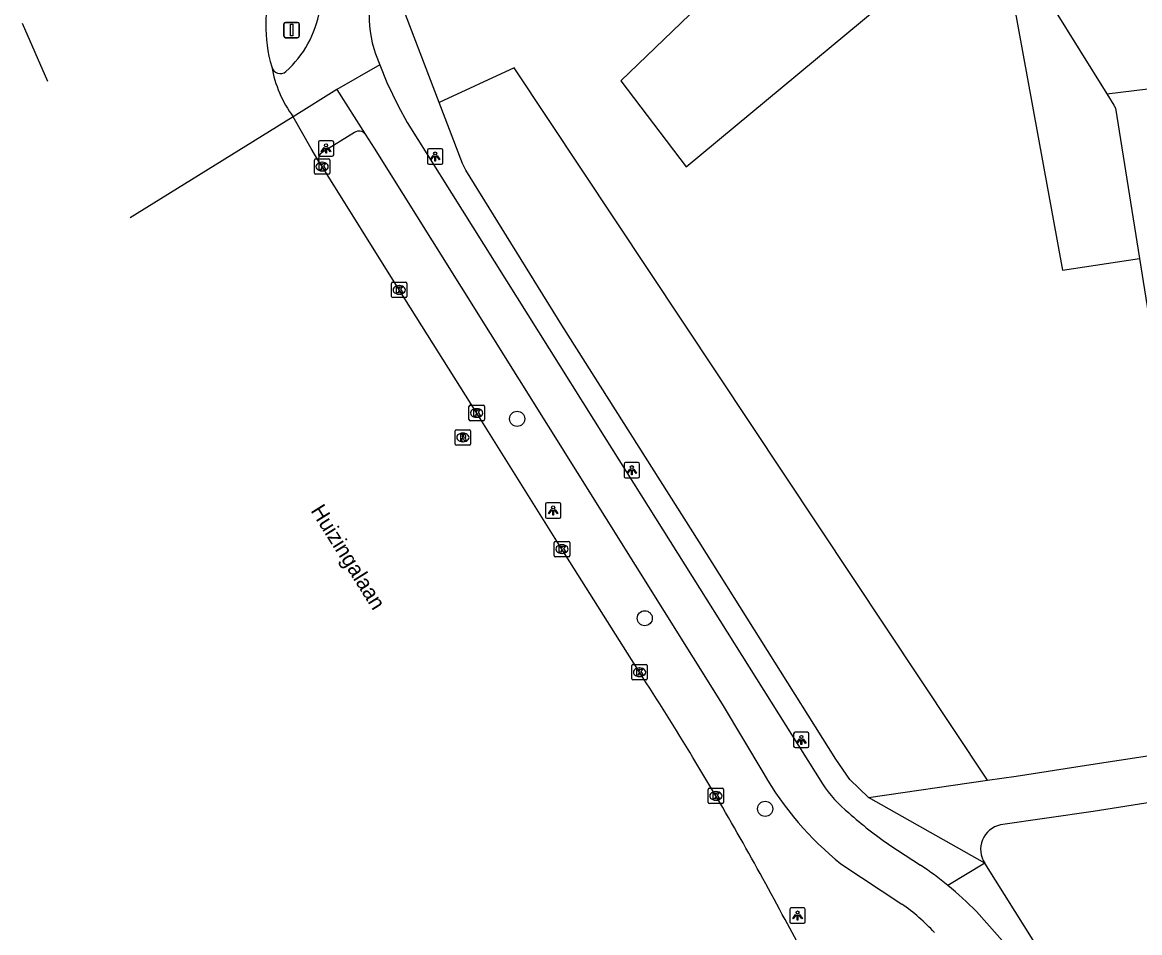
# Model space of a CAD drawing. Extents: x 160077 to 160945, y 386481 to 387498.
# Drawn here: x 160077 to 160149.7, y 387264.4 to 387323.5 of the extents above; entities that cross this region are included whole.
import ezdxf

# ---------------------------------------------------------------- set-up
doc = ezdxf.new("R2010")
doc.units = 0
for name, color, linetype in [('IMGEO_Boom', 7, 'Continuous'), ('IMGEO_Fietspad_gesloten', 7, 'Continuous'), ('IMGEO_Groenvoorziening', 7, 'Continuous'), ('IMGEO_Kolk', 7, 'Continuous'), ('IMGEO_Lichtpunt', 7, 'Continuous'), ('IMGEO_Openbare_ruimte_label', 7, 'Continuous'), ('IMGEO_OVBaan_gesloten', 7, 'Continuous'), ('IMGEO_Portaal', 7, 'Continuous'), ('IMGEO_Rijbaan_regionaal_gesloten', 7, 'Continuous'), ('IMGEO_Rioolput', 7, 'Continuous'), ('IMGEO_Voetpad_gesloten', 7, 'Continuous'), ('IMGEO_Voetpad_open', 7, 'Continuous')]:
    doc.layers.add(name, color=color, linetype=linetype)

msp = doc.modelspace()

# ---------------------------------------------------------------- linework, layer by layer
at = {"layer": 'IMGEO_Boom'}
for centre in [(160109.211, 387297.771), (160117.506, 387284.806), (160125.333, 387272.416)]:
    msp.add_circle(centre, 0.489, dxfattribs=at)
at = {"layer": 'IMGEO_Fietspad_gesloten'}
for points in [[(160100.002, 387321.494), (160100.284, 387320.786)], [(160100.284, 387320.786), (160097.499, 387319.172)], [(160100.284, 387320.786), (160100.745, 387319.628), (160101.473, 387318.123), (160102.066, 387317.033), (160114.864, 387296.614), (160129.06, 387274.05)], [(160097.499, 387319.172), (160094.645, 387317.405)], [(160097.499, 387319.172), (160099.341, 387316.28)], [(160099.341, 387316.28), (160099.906, 387315.367), (160122.542, 387279.222), (160125.245, 387274.696)], [(160133.446, 387270.057), (160135.422, 387268.762)], [(160130.263, 387268.841), (160134.209, 387266.225)], [(160139.072, 387265.739), (160141.59, 387262.907), (160159.923, 387233.732), (160180.666, 387200.687)]]:
    msp.add_lwpolyline(points, dxfattribs=at)
for centre, radius, start, end in [((160089.532, 387325.502), 6.943, 312.05353, 350.24641), ((160107.216, 387323.943), 7.619, 176.26365, 198.74719), ((160093.812, 387320.778), 0.568, 191.60509, 310.6373), ((160143.301, 387285.093), 20.836, 209.93439, 231.26175), ((160135.924, 387278.518), 8.191, 213.06275, 231.00172), ((160147.775, 387291.107), 25.464, 228.10281, 235.75693), ((160122.078, 387248.926), 23.906, 50.71415, 56.06934), ((160122.195, 387249.07), 23.721, 44.64408, 50.7134), ((160127.505, 387256.376), 11.914, 42.12371, 55.75976)]:
    msp.add_arc(centre, radius, start, end, dxfattribs=at)
at = {"layer": 'IMGEO_Groenvoorziening'}
for points in [[(160133.36, 387341.629), (160133.048, 387341.231), (160135, 387338.07), (160115.943, 387319.74), (160120.193, 387314.153), (160139.057, 387329.83), (160141.124, 387326.758), (160144.653, 387307.431), (160149.674, 387308.189)], [(160140.514, 387330.194), (160147.536, 387318.896)], [(160139.785, 387274.28), (160109.024, 387320.599), (160104.15, 387318.343)]]:
    msp.add_lwpolyline(points, dxfattribs=at)
at = {"layer": 'IMGEO_Kolk'}
for p, q in [((160096.03, 387313.741), (160096.03, 387314.593)), ((160096.105, 387314.667), (160096.957, 387314.667)), ((160097.031, 387314.593), (160097.031, 387313.741)), ((160096.541, 387313.887), (160096.516, 387313.887)), ((160096.518, 387314.447), (160096.543, 387314.447)), ((160096.957, 387313.667), (160096.105, 387313.667)), ((160101.12, 387306.651), (160101.972, 387306.651)), ((160101.045, 387305.725), (160101.045, 387306.577)), ((160101.556, 387305.871), (160101.531, 387305.871)), ((160101.533, 387306.431), (160101.558, 387306.431)), ((160102.046, 387306.577), (160102.046, 387305.725)), ((160101.972, 387305.651), (160101.12, 387305.651)), ((160106.155, 387298.648), (160107.007, 387298.648)), ((160106.08, 387297.722), (160106.08, 387298.574)), ((160106.568, 387298.428), (160106.593, 387298.428)), ((160107.081, 387298.574), (160107.081, 387297.722)), ((160107.007, 387297.648), (160106.155, 387297.648)), ((160106.591, 387297.868), (160106.566, 387297.868)), ((160111.625, 387288.875), (160111.625, 387289.727)), ((160111.7, 387289.801), (160112.552, 387289.801)), ((160112.113, 387289.581), (160112.138, 387289.581)), ((160112.626, 387289.727), (160112.626, 387288.875)), ((160112.552, 387288.801), (160111.7, 387288.801)), ((160112.136, 387289.021), (160112.111, 387289.021)), ((160116.664, 387280.872), (160116.664, 387281.724)), ((160116.739, 387281.798), (160117.591, 387281.798)), ((160117.152, 387281.578), (160117.177, 387281.578)), ((160117.665, 387281.724), (160117.665, 387280.872)), ((160117.591, 387280.798), (160116.739, 387280.798)), ((160117.175, 387281.018), (160117.15, 387281.018)), ((160121.63, 387272.831), (160121.63, 387273.683)), ((160121.705, 387273.757), (160122.557, 387273.757)), ((160122.118, 387273.537), (160122.143, 387273.537)), ((160122.631, 387273.683), (160122.631, 387272.831)), ((160122.557, 387272.757), (160121.705, 387272.757)), ((160122.141, 387272.977), (160122.116, 387272.977))]:
    msp.add_line(p, q, dxfattribs=at)
for points in [[(160096.03, 387313.741), (160096.03, 387314.593)], [(160096.105, 387314.667), (160096.957, 387314.667)], [(160097.031, 387314.593), (160097.031, 387313.741)], [(160096.351, 387314.367), (160096.474, 387314.367), (160096.474, 387314.216), (160096.604, 387314.367), (160096.768, 387314.367), (160096.622, 387314.216), (160096.775, 387313.967), (160096.623, 387313.967), (160096.538, 387314.131), (160096.474, 387314.064), (160096.474, 387313.967), (160096.351, 387313.967), (160096.351, 387314.367)], [(160096.957, 387313.667), (160096.105, 387313.667)], [(160101.12, 387306.651), (160101.972, 387306.651)], [(160101.045, 387305.725), (160101.045, 387306.577)], [(160101.366, 387306.351), (160101.489, 387306.351), (160101.489, 387306.2), (160101.619, 387306.351), (160101.783, 387306.351), (160101.637, 387306.2), (160101.79, 387305.951), (160101.638, 387305.951), (160101.553, 387306.115), (160101.489, 387306.048), (160101.489, 387305.951), (160101.366, 387305.951), (160101.366, 387306.351)], [(160102.046, 387306.577), (160102.046, 387305.725)], [(160101.972, 387305.651), (160101.12, 387305.651)], [(160106.155, 387298.648), (160107.007, 387298.648)], [(160106.08, 387297.722), (160106.08, 387298.574)], [(160106.401, 387298.348), (160106.524, 387298.348), (160106.524, 387298.197), (160106.654, 387298.348), (160106.818, 387298.348), (160106.672, 387298.197), (160106.825, 387297.948), (160106.673, 387297.948), (160106.588, 387298.112), (160106.524, 387298.045), (160106.524, 387297.948), (160106.401, 387297.948), (160106.401, 387298.348)], [(160107.081, 387298.574), (160107.081, 387297.722)], [(160107.007, 387297.648), (160106.155, 387297.648)], [(160111.625, 387288.875), (160111.625, 387289.727)], [(160111.7, 387289.801), (160112.552, 387289.801)], [(160111.946, 387289.501), (160112.069, 387289.501), (160112.069, 387289.35), (160112.199, 387289.501), (160112.363, 387289.501), (160112.217, 387289.35), (160112.37, 387289.101), (160112.218, 387289.101), (160112.133, 387289.265), (160112.069, 387289.198), (160112.069, 387289.101), (160111.946, 387289.101), (160111.946, 387289.501)], [(160112.626, 387289.727), (160112.626, 387288.875)], [(160112.552, 387288.801), (160111.7, 387288.801)], [(160116.664, 387280.872), (160116.664, 387281.724)], [(160116.739, 387281.798), (160117.591, 387281.798)], [(160116.985, 387281.498), (160117.108, 387281.498), (160117.108, 387281.347), (160117.238, 387281.498), (160117.402, 387281.498), (160117.256, 387281.347), (160117.409, 387281.098), (160117.257, 387281.098), (160117.172, 387281.262), (160117.108, 387281.195), (160117.108, 387281.098), (160116.985, 387281.098), (160116.985, 387281.498)], [(160117.665, 387281.724), (160117.665, 387280.872)], [(160117.591, 387280.798), (160116.739, 387280.798)], [(160121.63, 387272.831), (160121.63, 387273.683)], [(160121.705, 387273.757), (160122.557, 387273.757)], [(160121.951, 387273.457), (160122.074, 387273.457), (160122.074, 387273.306), (160122.204, 387273.457), (160122.368, 387273.457), (160122.222, 387273.306), (160122.375, 387273.057), (160122.223, 387273.057), (160122.138, 387273.221), (160122.074, 387273.154), (160122.074, 387273.057), (160121.951, 387273.057), (160121.951, 387273.457)], [(160122.631, 387273.683), (160122.631, 387272.831)], [(160122.557, 387272.757), (160121.705, 387272.757)]]:
    msp.add_lwpolyline(points, dxfattribs=at)
for centre, start, end in [((160096.107, 387314.591), 91.55205, 178.44795), ((160096.107, 387314.591), 91.55205, 178.44795), ((160096.955, 387314.591), 1.55205, 88.44795), ((160096.955, 387314.591), 1.55205, 88.44795), ((160096.107, 387313.743), 181.55205, 268.44795), ((160096.107, 387313.743), 181.55205, 268.44795), ((160096.955, 387313.743), 271.55205, 358.44795), ((160096.955, 387313.743), 271.55205, 358.44795), ((160101.122, 387306.575), 91.55205, 178.44795), ((160101.122, 387306.575), 91.55205, 178.44795), ((160101.97, 387306.575), 1.55205, 88.44795), ((160101.97, 387306.575), 1.55205, 88.44795), ((160101.122, 387305.727), 181.55205, 268.44795), ((160101.122, 387305.727), 181.55205, 268.44795), ((160101.97, 387305.727), 271.55205, 358.44795), ((160101.97, 387305.727), 271.55205, 358.44795), ((160106.157, 387298.572), 91.55205, 178.44795), ((160106.157, 387298.572), 91.55205, 178.44795), ((160107.005, 387298.572), 1.55205, 88.44795), ((160107.005, 387298.572), 1.55205, 88.44795), ((160106.157, 387297.724), 181.55205, 268.44795), ((160106.157, 387297.724), 181.55205, 268.44795), ((160107.005, 387297.724), 271.55205, 358.44795), ((160107.005, 387297.724), 271.55205, 358.44795), ((160111.702, 387289.725), 91.55205, 178.44795), ((160111.702, 387289.725), 91.55205, 178.44795), ((160112.55, 387289.725), 1.55205, 88.44795), ((160112.55, 387289.725), 1.55205, 88.44795), ((160111.702, 387288.877), 181.55205, 268.44795), ((160111.702, 387288.877), 181.55205, 268.44795), ((160112.55, 387288.877), 271.55205, 358.44795), ((160112.55, 387288.877), 271.55205, 358.44795), ((160116.741, 387281.722), 91.55205, 178.44795), ((160116.741, 387281.722), 91.55205, 178.44795), ((160117.589, 387281.722), 1.55205, 88.44795), ((160117.589, 387281.722), 1.55205, 88.44795), ((160116.741, 387280.874), 181.55205, 268.44795), ((160116.741, 387280.874), 181.55205, 268.44795), ((160117.589, 387280.874), 271.55205, 358.44795), ((160117.589, 387280.874), 271.55205, 358.44795), ((160121.707, 387273.681), 91.55205, 178.44795), ((160121.707, 387273.681), 91.55205, 178.44795), ((160122.555, 387273.681), 1.55205, 88.44795), ((160122.555, 387273.681), 1.55205, 88.44795), ((160121.707, 387272.833), 181.55205, 268.44795), ((160121.707, 387272.833), 181.55205, 268.44795), ((160122.555, 387272.833), 271.55205, 358.44795), ((160122.555, 387272.833), 271.55205, 358.44795)]:
    msp.add_arc(centre, 0.0765, start, end, dxfattribs=at)
for centre, major_axis, ratio, start_param, end_param in [((160096.517, 387314.167), (-0.387, 0.002), 0.722429, 4.712389, 7.853982), ((160096.542, 387314.167), (-0.39, 0.002), 0.717154, 1.570796, 4.712389), ((160101.532, 387306.151), (-0.387, 0.002), 0.722429, 4.712389, 7.853982), ((160101.557, 387306.151), (-0.39, 0.002), 0.717154, 1.570796, 4.712389), ((160106.567, 387298.148), (-0.387, 0.002), 0.722429, 4.712389, 7.853982), ((160106.592, 387298.148), (-0.39, 0.002), 0.717154, 1.570796, 4.712389), ((160112.112, 387289.301), (-0.387, 0.002), 0.722429, 4.712389, 7.853982), ((160112.137, 387289.301), (-0.39, 0.002), 0.717154, 1.570796, 4.712389), ((160117.151, 387281.298), (-0.387, 0.002), 0.722429, 4.712389, 7.853982), ((160117.176, 387281.298), (-0.39, 0.002), 0.717154, 1.570796, 4.712389), ((160122.117, 387273.257), (-0.387, 0.002), 0.722429, 4.712389, 7.853982), ((160122.142, 387273.257), (-0.39, 0.002), 0.717154, 1.570796, 4.712389)]:
    msp.add_ellipse(centre, major_axis=major_axis, ratio=ratio, start_param=start_param, end_param=end_param, dxfattribs=at)
at = {"layer": 'IMGEO_Lichtpunt'}
for p, q in [((160096.29, 387315.75), (160096.29, 387314.943)), ((160096.29, 387315.75), (160096.29, 387314.943)), ((160097.192, 387315.845), (160096.384, 387315.845)), ((160097.192, 387315.845), (160096.384, 387315.845)), ((160097.286, 387314.943), (160097.286, 387315.75)), ((160097.286, 387314.943), (160097.286, 387315.75)), ((160104.286, 387315.321), (160103.478, 387315.321)), ((160104.286, 387315.321), (160103.478, 387315.321)), ((160096.384, 387314.849), (160097.192, 387314.849)), ((160096.384, 387314.849), (160097.192, 387314.849)), ((160103.384, 387315.226), (160103.384, 387314.419)), ((160103.384, 387315.226), (160103.384, 387314.419)), ((160104.38, 387314.419), (160104.38, 387315.226)), ((160104.38, 387314.419), (160104.38, 387315.226)), ((160103.478, 387314.325), (160104.286, 387314.325)), ((160103.478, 387314.325), (160104.286, 387314.325)), ((160116.166, 387294.833), (160116.166, 387294.026)), ((160116.166, 387294.833), (160116.166, 387294.026)), ((160117.068, 387294.928), (160116.26, 387294.928)), ((160117.068, 387294.928), (160116.26, 387294.928)), ((160117.162, 387294.026), (160117.162, 387294.833)), ((160117.162, 387294.026), (160117.162, 387294.833)), ((160116.26, 387293.932), (160117.068, 387293.932)), ((160116.26, 387293.932), (160117.068, 387293.932)), ((160111.053, 387292.215), (160111.053, 387291.408)), ((160111.053, 387292.215), (160111.053, 387291.408)), ((160111.955, 387292.31), (160111.147, 387292.31)), ((160111.955, 387292.31), (160111.147, 387292.31)), ((160112.049, 387291.408), (160112.049, 387292.215)), ((160112.049, 387291.408), (160112.049, 387292.215)), ((160111.147, 387291.314), (160111.955, 387291.314)), ((160111.147, 387291.314), (160111.955, 387291.314)), ((160127.186, 387277.296), (160127.186, 387276.489)), ((160127.186, 387277.296), (160127.186, 387276.489)), ((160128.088, 387277.391), (160127.28, 387277.391)), ((160128.088, 387277.391), (160127.28, 387277.391)), ((160128.182, 387276.489), (160128.182, 387277.296)), ((160128.182, 387276.489), (160128.182, 387277.296)), ((160127.28, 387276.395), (160128.088, 387276.395)), ((160127.28, 387276.395), (160128.088, 387276.395)), ((160127.841, 387265.978), (160127.033, 387265.978)), ((160127.841, 387265.978), (160127.033, 387265.978)), ((160126.939, 387265.883), (160126.939, 387265.076)), ((160126.939, 387265.883), (160126.939, 387265.076)), ((160127.935, 387265.076), (160127.935, 387265.883)), ((160127.935, 387265.076), (160127.935, 387265.883)), ((160127.033, 387264.982), (160127.841, 387264.982)), ((160127.033, 387264.982), (160127.841, 387264.982))]:
    msp.add_line(p, q, dxfattribs=at)
for points in [[(160096.664, 387315.414), (160096.703, 387315.386), (160096.515, 387315.124), (160096.477, 387315.151), (160096.664, 387315.414)], [(160096.766, 387315.366), (160096.813, 387315.366), (160096.813, 387315.044), (160096.766, 387315.044), (160096.766, 387315.366)], [(160096.876, 387315.386), (160096.914, 387315.413), (160097.101, 387315.151), (160097.062, 387315.123), (160096.876, 387315.386)], [(160103.758, 387314.89), (160103.797, 387314.862), (160103.609, 387314.6), (160103.571, 387314.627), (160103.758, 387314.89)], [(160103.86, 387314.842), (160103.907, 387314.842), (160103.907, 387314.52), (160103.86, 387314.52), (160103.86, 387314.842)], [(160103.97, 387314.862), (160104.008, 387314.889), (160104.195, 387314.627), (160104.156, 387314.599), (160103.97, 387314.862)], [(160116.54, 387294.497), (160116.579, 387294.469), (160116.391, 387294.207), (160116.353, 387294.234), (160116.54, 387294.497)], [(160116.642, 387294.449), (160116.689, 387294.449), (160116.689, 387294.127), (160116.642, 387294.127), (160116.642, 387294.449)], [(160116.752, 387294.469), (160116.79, 387294.496), (160116.977, 387294.234), (160116.938, 387294.206), (160116.752, 387294.469)], [(160111.427, 387291.879), (160111.466, 387291.851), (160111.278, 387291.589), (160111.24, 387291.616), (160111.427, 387291.879)], [(160111.529, 387291.831), (160111.576, 387291.831), (160111.576, 387291.509), (160111.529, 387291.509), (160111.529, 387291.831)], [(160111.639, 387291.851), (160111.677, 387291.878), (160111.864, 387291.616), (160111.825, 387291.588), (160111.639, 387291.851)], [(160127.56, 387276.96), (160127.599, 387276.932), (160127.411, 387276.67), (160127.373, 387276.697), (160127.56, 387276.96)], [(160127.662, 387276.912), (160127.709, 387276.912), (160127.709, 387276.59), (160127.662, 387276.59), (160127.662, 387276.912)], [(160127.772, 387276.932), (160127.81, 387276.959), (160127.997, 387276.697), (160127.958, 387276.669), (160127.772, 387276.932)], [(160127.313, 387265.547), (160127.352, 387265.519), (160127.164, 387265.257), (160127.126, 387265.284), (160127.313, 387265.547)], [(160127.415, 387265.499), (160127.462, 387265.499), (160127.462, 387265.177), (160127.415, 387265.177), (160127.415, 387265.499)], [(160127.525, 387265.519), (160127.563, 387265.546), (160127.75, 387265.284), (160127.711, 387265.256), (160127.525, 387265.519)]]:
    msp.add_lwpolyline(points, dxfattribs=at)
for centre in [(160096.789, 387315.548), (160103.883, 387315.024), (160116.665, 387294.631), (160111.552, 387292.013), (160127.685, 387277.094), (160127.438, 387265.681)]:
    msp.add_circle(centre, 0.0994, dxfattribs=at)
for centre, start, end in [((160096.384, 387315.75), 90, 180), ((160096.384, 387315.75), 90, 180), ((160097.192, 387315.75), 0, 90), ((160097.192, 387315.75), 0, 90), ((160103.478, 387315.226), 90, 180), ((160103.478, 387315.226), 90, 180), ((160104.286, 387315.226), 0, 90), ((160104.286, 387315.226), 0, 90), ((160096.384, 387314.943), 180, 270), ((160096.384, 387314.943), 180, 270), ((160097.192, 387314.943), 270, 0), ((160097.192, 387314.943), 270, 360), ((160103.478, 387314.419), 180, 270), ((160103.478, 387314.419), 180, 270), ((160104.286, 387314.419), 270, 0), ((160104.286, 387314.419), 270, 360), ((160116.26, 387294.833), 90, 180), ((160116.26, 387294.833), 90, 180), ((160117.068, 387294.833), 0, 90), ((160117.068, 387294.833), 0, 90), ((160116.26, 387294.026), 180, 270), ((160116.26, 387294.026), 180, 270), ((160117.068, 387294.026), 270, 0), ((160117.068, 387294.026), 270, 360), ((160111.147, 387292.215), 90, 180), ((160111.147, 387292.215), 90, 180), ((160111.955, 387292.215), 0, 90), ((160111.955, 387292.215), 0, 90), ((160111.147, 387291.408), 180, 270), ((160111.147, 387291.408), 180, 270), ((160111.955, 387291.408), 270, 0), ((160111.955, 387291.408), 270, 360), ((160127.28, 387277.296), 90, 180), ((160127.28, 387277.296), 90, 180), ((160128.088, 387277.296), 0, 90), ((160128.088, 387277.296), 0, 90), ((160127.28, 387276.489), 180, 270), ((160127.28, 387276.489), 180, 270), ((160128.088, 387276.489), 270, 0), ((160128.088, 387276.489), 270, 360), ((160127.033, 387265.883), 90, 180), ((160127.033, 387265.883), 90, 180), ((160127.841, 387265.883), 0, 90), ((160127.841, 387265.883), 0, 90), ((160127.033, 387265.076), 180, 270), ((160127.033, 387265.076), 180, 270), ((160127.841, 387265.076), 270, 0), ((160127.841, 387265.076), 270, 360)]:
    msp.add_arc(centre, 0.0946, start, end, dxfattribs=at)
at = {"layer": 'IMGEO_OVBaan_gesloten'}
msp.add_lwpolyline([(160078.711, 387319.696), (160077.046, 387323.47)], dxfattribs=at)
at = {"layer": 'IMGEO_Portaal'}
for p, q in [((160094.051, 387322.646), (160094.051, 387323.446)), ((160094.051, 387323.446), (160094.051, 387322.646)), ((160094.151, 387323.546), (160094.941, 387323.546)), ((160094.941, 387323.546), (160094.151, 387323.546)), ((160095.041, 387323.446), (160095.041, 387322.646)), ((160095.041, 387322.646), (160095.041, 387323.446)), ((160094.941, 387322.546), (160094.151, 387322.546)), ((160094.151, 387322.546), (160094.941, 387322.546))]:
    msp.add_line(p, q, dxfattribs=at)
msp.add_lwpolyline([(160094.471, 387323.421), (160094.621, 387323.421), (160094.621, 387322.671), (160094.471, 387322.671), (160094.471, 387323.421)], dxfattribs=at)
for centre, start, end in [((160094.151, 387323.446), 90, 180), ((160094.151, 387323.446), 90, 180), ((160094.941, 387323.446), 0, 90), ((160094.941, 387323.446), 360, 90), ((160094.151, 387322.646), 180, 270), ((160094.151, 387322.646), 180, 270), ((160094.941, 387322.646), 270, 0), ((160094.941, 387322.646), 270, 0)]:
    msp.add_arc(centre, 0.1, start, end, dxfattribs=at)
at = {"layer": 'IMGEO_Rijbaan_regionaal_gesloten'}
for points in [[(160094.645, 387317.405), (160084.061, 387310.833)], [(160096.318, 387314.501), (160095.816, 387315.349), (160094.645, 387317.405)], [(160117.165, 387281.298), (160112.126, 387289.301), (160106.581, 387298.148), (160101.546, 387306.151), (160096.531, 387314.167), (160096.318, 387314.501)], [(160162.84, 387197.364), (160156.514, 387209.228), (160147.814, 387225.477), (160145.887, 387229.105), (160141.506, 387237.352), (160136.583, 387246.579), (160132.596, 387254.018), (160128.172, 387262.367), (160126.625, 387265.218)]]:
    msp.add_lwpolyline(points, dxfattribs=at)
for centre, radius, start, end in [((160102.272, 387323.327), 9.402, 161.88523, 196.45325), ((160100.986, 387322.035), 7.852, 190.0593, 216.13828), ((159937.316, 387164.654), 214.363, 31.21729, 32.96613), ((159936.055, 387163.96), 215.801, 27.98356, 31.20124)]:
    msp.add_arc(centre, radius, start, end, dxfattribs=at)
at = {"layer": 'IMGEO_Rioolput'}
for p, q in [((160105.183, 387296.133), (160105.183, 387296.985)), ((160105.258, 387297.059), (160106.11, 387297.059)), ((160105.671, 387296.839), (160105.696, 387296.839)), ((160106.184, 387296.985), (160106.184, 387296.133)), ((160106.11, 387296.059), (160105.258, 387296.059)), ((160105.694, 387296.279), (160105.669, 387296.279))]:
    msp.add_line(p, q, dxfattribs=at)
for points in [[(160105.183, 387296.133), (160105.183, 387296.985)], [(160105.258, 387297.059), (160106.11, 387297.059)], [(160105.772, 387296.757), (160105.52, 387296.759), (160105.52, 387296.359)], [(160105.52, 387296.359), (160105.644, 387296.359), (160105.644, 387296.521), (160105.655, 387296.521)], [(160105.698, 387296.678), (160105.644, 387296.678), (160105.644, 387296.597)], [(160105.644, 387296.597), (160105.696, 387296.597)], [(160105.702, 387296.492), (160105.773, 387296.359), (160105.913, 387296.359), (160105.848, 387296.485)], [(160106.184, 387296.985), (160106.184, 387296.133)], [(160106.11, 387296.059), (160105.258, 387296.059)]]:
    msp.add_lwpolyline(points, dxfattribs=at)
for centre, radius, start, end in [((160105.26, 387296.983), 0.0765, 91.55205, 178.44795), ((160105.26, 387296.983), 0.0765, 91.55205, 178.44795), ((160105.654, 387296.468), 0.0533, 26.02933, 88.69889), ((160105.68, 387296.786), 0.19, 274.7715, 282.96867), ((160105.704, 387296.582), 0.0964, 77.00612, 93.18647), ((160105.718, 387296.639), 0.0378, 276.66336, 79.67722), ((160105.771, 387296.647), 0.109, 350.36119, 89.41601), ((160105.769, 387296.647), 0.112, 277.58423, 350.98172), ((160105.753, 387296.432), 0.108, 29.51342, 73.79051), ((160106.108, 387296.983), 0.0765, 1.55205, 88.44795), ((160106.108, 387296.983), 0.0765, 1.55205, 88.44795), ((160105.26, 387296.135), 0.0765, 181.55205, 268.44795), ((160105.26, 387296.135), 0.0765, 181.55205, 268.44795), ((160106.108, 387296.135), 0.0765, 271.55205, 358.44795), ((160106.108, 387296.135), 0.0765, 271.55205, 358.44795)]:
    msp.add_arc(centre, radius, start, end, dxfattribs=at)
for centre, major_axis, ratio, start_param, end_param in [((160105.67, 387296.559), (-0.387, 0.002), 0.722429, 4.712389, 7.853982), ((160105.695, 387296.559), (-0.39, 0.002), 0.717154, 1.570796, 4.712389)]:
    msp.add_ellipse(centre, major_axis=major_axis, ratio=ratio, start_param=start_param, end_param=end_param, dxfattribs=at)
at = {"layer": 'IMGEO_Voetpad_gesloten'}
msp.add_lwpolyline([(160098.648, 387316.391), (160096.542, 387315.086)], dxfattribs=at)
for centre, radius, start, end in [((160098.93, 387315.935), 0.536, 40.01819, 121.78191), ((160096.794, 387314.654), 0.5, 120.25209, 197.84362)]:
    msp.add_arc(centre, radius, start, end, dxfattribs=at)
at = {"layer": 'IMGEO_Voetpad_open'}
for points in [[(160104.15, 387318.343), (160101.386, 387325.554)], [(160147.536, 387318.896), (160170.455, 387321.701)], [(160132.053, 387273.157), (160130.837, 387274.317), (160129.934, 387275.653), (160121.033, 387289.768), (160112.11, 387303.867), (160105.879, 387313.937), (160105.669, 387314.379), (160104.15, 387318.343)], [(160147.536, 387318.896), (160147.999, 387318.151), (160148.112, 387317.97), (160149.674, 387308.189)], [(160149.674, 387308.189), (160154.726, 387276.548)], [(160139.785, 387274.28), (160141.641, 387274.55), (160146.224, 387275.251), (160154.726, 387276.548)], [(160132.053, 387273.157), (160139.785, 387274.28)], [(160155.14, 387273.594), (160146.656, 387272.235), (160140.627, 387271.369)], [(160139.615, 387268.878), (160132.053, 387273.157)], [(160139.615, 387268.878), (160137.215, 387267.43)], [(160179.769, 387204.942), (160161.126, 387234.638), (160142.864, 387263.696), (160139.615, 387268.878)]]:
    msp.add_lwpolyline(points, dxfattribs=at)
msp.add_arc((160140.963, 387269.781), 1.623, 101.95515, 213.82472, dxfattribs=at)

# ---------------------------------------------------------------- texts
at = {"layer": 'IMGEO_Openbare_ruimte_label'}
msp.add_text('Huizingalaan', height=1, rotation=302.08436, dxfattribs=at).set_placement((160095.758, 387291.804))

doc.saveas('drawing.dxf')
